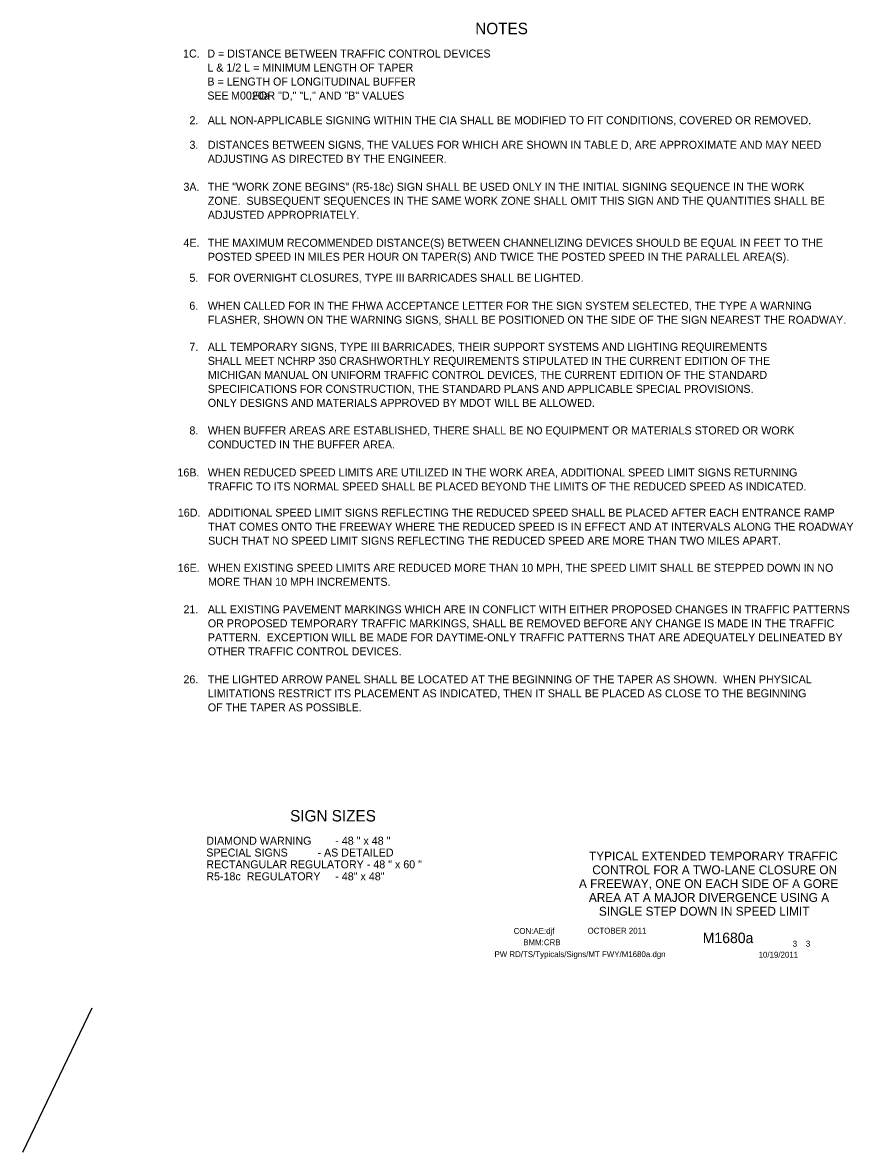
# Model space of a CAD drawing. Extents: x 16486 to 19505, y 5576 to 6998.
# Drawn here: x 18633 to 19505, y 5729 to 6915 of the extents above; entities that cross this region are included whole.
import ezdxf

# ---------------------------------------------------------------- set-up
doc = ezdxf.new("R2010")
doc.units = 0
for name, color, linetype in [('BORDER', 7, 'Continuous'), ('BORDER_SIGNAL_WO', 7, 'Continuous'), ('TYPICAL_TEXT_DIMEN_PR', 7, 'Continuous')]:
    doc.layers.add(name, color=color, linetype=linetype)

msp = doc.modelspace()

# ---------------------------------------------------------------- linework, layer by layer
at = {"layer": 'TYPICAL_TEXT_DIMEN_PR'}
msp.add_line((18705.8, 5880), (18633.1, 5728.7), dxfattribs=at)

# ---------------------------------------------------------------- texts
at = {"layer": 'BORDER'}
for s, p in [('TYPICAL EXTENDED TEMPORARY TRAFFIC', (19227.8, 6035.2)), ('CONTROL FOR A TWO-LANE CLOSURE ON', (19231.3, 6020.7)), ('A FREEWAY, ONE ON EACH SIDE OF A GORE', (19217.3, 6006.2)), ('AREA AT A MAJOR DIVERGENCE USING A', (19227.7, 5991.7)), ('SINGLE STEP DOWN IN SPEED LIMIT', (19238.2, 5977.2))]:
    msp.add_text(s, height=9.3, dxfattribs=at).set_placement(p)
at = {"layer": 'BORDER_SIGNAL_WO'}
for s, height, p in [('CON:AE:djf  ', 6.2, (19148.7, 5958.1)), ('    OCTOBER 2011    ', 6.2, (19217.1, 5958.3)), ('    M1680a   ', 11, (19330.9, 5948.4)), ('BMM:CRB   ', 6.2, (19158.8, 5946.2)), (' 3    3 ', 6.2, (19439.4, 5944.7)), ('PW RD/TS/Typicals/Signs/MT FWY/M1680a.dgn      ', 6.2, (19128.6, 5933.7)), ('10/19/2011    ', 6.2, (19405.9, 5933.1))]:
    msp.add_text(s, height=height, dxfattribs=at).set_placement(p)
at = {"layer": 'TYPICAL_TEXT_DIMEN_PR'}
for s, height, p in [('NOTES', 12, (19108.4, 6902.6)), ('1C.', 8.4, (18801.6, 6878.1)), ('D = DISTANCE BETWEEN TRAFFIC CONTROL DEVICES', 8.4, (18827.1, 6878.1)), ('L & 1/2 L = MINIMUM LENGTH OF TAPER', 8.4, (18827.1, 6863.4)), ('B = LENGTH OF LONGITUDINAL BUFFER', 8.4, (18827.1, 6848.7)), ('SEE        FOR "D," "L," AND "B" VALUES', 8.4, (18827.1, 6834)), ('M0020a', 8.4, (18852, 6834)), ('2.', 8.4, (18808.3, 6808.1)), ('ALL NON-APPLICABLE SIGNING WITHIN THE CIA SHALL BE MODIFIED TO FIT CONDITIONS, COVERED OR REMOVED.', 8.4, (18827.6, 6808.1)), ('3.', 8.4, (18808.3, 6782.3)), ('DISTANCES BETWEEN SIGNS, THE VALUES FOR WHICH ARE SHOWN IN TABLE D, ARE APPROXIMATE AND MAY NEED', 8.4, (18827.6, 6782.3)), ('ADJUSTING AS DIRECTED BY THE ENGINEER.', 8.4, (18827.6, 6767.6)), ('3A.', 8.4, (18802, 6738.2)), ('THE "WORK ZONE BEGINS" (R5-18c) SIGN SHALL BE USED ONLY IN THE INITIAL SIGNING SEQUENCE IN THE WORK', 8.4, (18827.6, 6738.2)), ('ZONE.  SUBSEQUENT SEQUENCES IN THE SAME WORK ZONE SHALL OMIT THIS SIGN AND THE QUANTITIES SHALL BE', 8.4, (18827.6, 6723.5)), ('ADJUSTED APPROPRIATELY.', 8.4, (18827.6, 6708.8)), ('4E.', 8.4, (18802, 6679.4)), ('THE MAXIMUM RECOMMENDED DISTANCE(S) BETWEEN CHANNELIZING DEVICES SHOULD BE EQUAL IN FEET TO THE', 8.4, (18827.6, 6679.4)), ('POSTED SPEED IN MILES PER HOUR ON TAPER(S) AND TWICE THE POSTED SPEED IN THE PARALLEL AREA(S).', 8.4, (18827.6, 6664.7)), ('5.', 8.4, (18808.3, 6642.7)), ('FOR OVERNIGHT CLOSURES, TYPE III BARRICADES SHALL BE LIGHTED.', 8.4, (18827.6, 6642.7)), ('6.', 8.4, (18808.2, 6613.3)), ('WHEN CALLED FOR IN THE FHWA ACCEPTANCE LETTER FOR THE SIGN SYSTEM SELECTED, THE TYPE A WARNING ', 8.4, (18827.6, 6613.3)), ('FLASHER, SHOWN ON THE WARNING SIGNS, SHALL BE POSITIONED ON THE SIDE OF THE SIGN NEAREST THE ROADWAY.', 8.4, (18827.6, 6598.6)), ('7.', 8.4, (18808.2, 6570.2)), ('ALL TEMPORARY SIGNS, TYPE III BARRICADES, THEIR SUPPORT SYSTEMS AND LIGHTING REQUIREMENTS', 8.4, (18827.6, 6570.2)), ('SHALL MEET NCHRP 350 CRASHWORTHLY REQUIREMENTS STIPULATED IN THE CURRENT EDITION OF THE', 8.4, (18827.6, 6555.5)), ('MICHIGAN MANUAL ON UNIFORM TRAFFIC CONTROL DEVICES, THE CURRENT EDITION OF THE STANDARD', 8.4, (18827.6, 6540.8)), ('SPECIFICATIONS FOR CONSTRUCTION, THE STANDARD PLANS AND APPLICABLE SPECIAL PROVISIONS.', 8.4, (18827.6, 6526.1)), ('ONLY DESIGNS AND MATERIALS APPROVED BY MDOT WILL BE ALLOWED.', 8.4, (18827.6, 6511.4)), ('8.', 8.4, (18808.3, 6482.4)), ('WHEN BUFFER AREAS ARE ESTABLISHED, THERE SHALL BE NO EQUIPMENT OR MATERIALS STORED OR WORK     ', 8.4, (18827.6, 6482.4)), ('CONDUCTED IN THE BUFFER AREA.', 8.4, (18827.6, 6467.7)), ('16B.', 8.4, (18795.7, 6438.3)), ('WHEN REDUCED SPEED LIMITS ARE UTILIZED IN THE WORK AREA, ADDITIONAL SPEED LIMIT SIGNS RETURNING', 8.4, (18827.6, 6438.3)), ('TRAFFIC TO ITS NORMAL SPEED SHALL BE PLACED BEYOND THE LIMITS OF THE REDUCED SPEED AS INDICATED.', 8.4, (18827.6, 6423.6)), ('16D.', 8.4, (18796.1, 6396.1)), ('ADDITIONAL SPEED LIMIT SIGNS REFLECTING THE REDUCED SPEED SHALL BE PLACED AFTER EACH ENTRANCE RAMP', 8.4, (18827.9, 6396.1)), ('THAT COMES ONTO THE FREEWAY WHERE THE REDUCED SPEED IS IN EFFECT AND AT INTERVALS ALONG THE ROADWAY', 8.4, (18827.9, 6381.4)), ('SUCH THAT NO SPEED LIMIT SIGNS REFLECTING THE REDUCED SPEED ARE MORE THAN TWO MILES APART.', 8.4, (18827.9, 6366.7)), ('16E.', 8.4, (18796, 6338.2)), ('WHEN EXISTING SPEED LIMITS ARE REDUCED MORE THAN 10 MPH, THE SPEED LIMIT SHALL BE STEPPED DOWN IN NO', 8.4, (18827.8, 6338.2)), ('MORE THAN 10 MPH INCREMENTS.', 8.4, (18827.8, 6323.5)), ('21.', 8.4, (18802, 6294.6)), ('ALL EXISTING PAVEMENT MARKINGS WHICH ARE IN CONFLICT WITH EITHER PROPOSED CHANGES IN TRAFFIC PATTERNS', 8.4, (18827.6, 6294.6)), ('OR PROPOSED TEMPORARY TRAFFIC MARKINGS, SHALL BE REMOVED BEFORE ANY CHANGE IS MADE IN THE TRAFFIC', 8.4, (18827.6, 6279.9)), ('PATTERN.  EXCEPTION WILL BE MADE FOR DAYTIME-ONLY TRAFFIC PATTERNS THAT ARE ADEQUATELY DELINEATED BY', 8.4, (18827.6, 6265.2)), ('OTHER TRAFFIC CONTROL DEVICES.', 8.4, (18827.6, 6250.5)), ('26.', 8.4, (18802, 6221.1)), ('THE LIGHTED ARROW PANEL SHALL BE LOCATED AT THE BEGINNING OF THE TAPER AS SHOWN.  WHEN PHYSICAL', 8.4, (18827.6, 6221.1)), ('LIMITATIONS RESTRICT ITS PLACEMENT AS INDICATED, THEN IT SHALL BE PLACED AS CLOSE TO THE BEGINNING', 8.4, (18827.6, 6206.4)), ('OF THE TAPER AS POSSIBLE.', 8.4, (18827.6, 6191.7)), ('SIGN SIZES', 12, (18914, 6076.1)), ('DIAMOND WARNING        - 48 " x 48 "', 8.4, (18826, 6051.7)), ('SPECIAL SIGNS          - AS DETAILED', 8.4, (18826, 6039.3)), ('RECTANGULAR REGULATORY - 48 " x 60 "', 8.4, (18826, 6026.9)), ('R5-18c  REGULATORY     - 48" x 48"', 8.4, (18826, 6014.3))]:
    msp.add_text(s, height=height, dxfattribs=at).set_placement(p)

doc.saveas('drawing.dxf')
